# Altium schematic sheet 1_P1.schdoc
size 307 x 518 mm; Symbol: Drawing-Symbol_A4; Device: Drawing-Symbol_A4; @Project Name: LED tower pcb; @Page Count: 1; @Update Date: 2025-07-10; @Create Date: 2025-07-10; @Schematic Name: Schematic3; @Page No: 1; @Page Name: P1; Company: EasyEDA.com; Version: V1.0; Page Size: A4; @Create Time: 04:32:52; @Update Time: 00:32:52; Width: 1170; Height: 2000; Region Start: 1; X Region Count: 6; Y Region Count: 4; Blade Width: 10; Title Block Position: 3; @Board Name: Board3
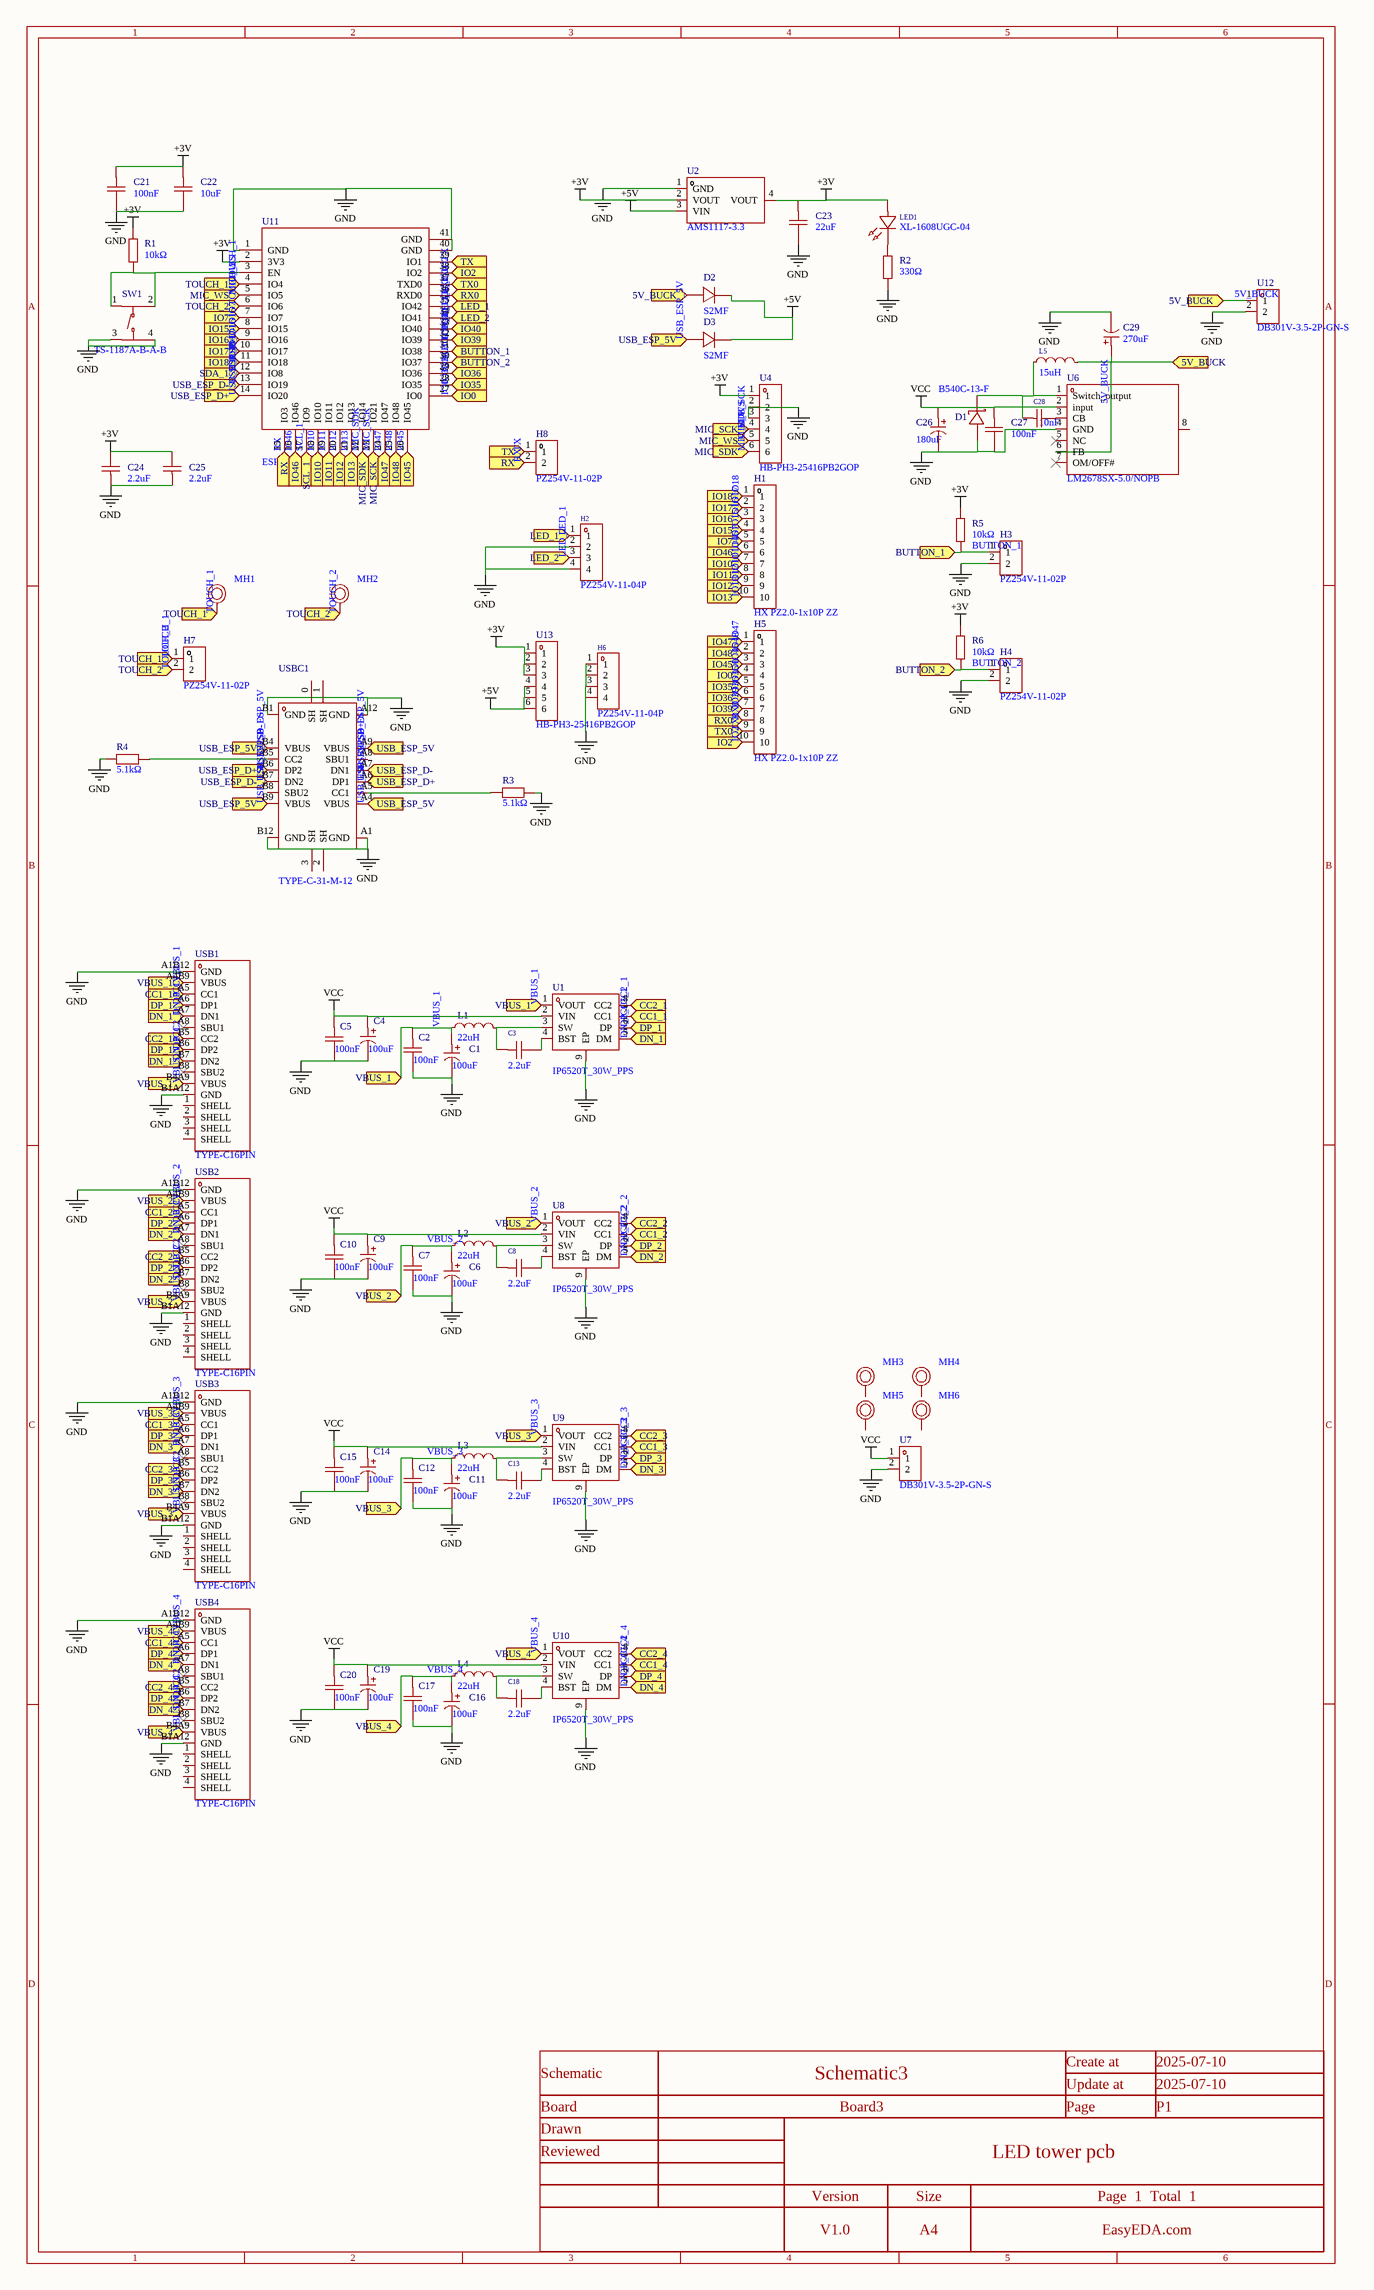
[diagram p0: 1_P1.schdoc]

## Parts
C1  100uF  [CAP-SMD_BD6.3-L6.6-W6.6-LS7.4-FD]
C2  100nF  [C0603]
C3  2.2uF  [C0603]
C4  100uF  [CAP-SMD_BD6.3-L6.6-W6.6-LS7.4-FD]
C5  100nF  [C0603]
C6  100uF  [CAP-SMD_BD6.3-L6.6-W6.6-LS7.4-FD]
C7  100nF  [C0603]
C8  2.2uF  [C0603]
C9  100uF  [CAP-SMD_BD6.3-L6.6-W6.6-LS7.4-FD]
C10  100nF  [C0603]
C11  100uF  [CAP-SMD_BD6.3-L6.6-W6.6-LS7.4-FD]
C12  100nF  [C0603]
C13  2.2uF  [C0603]
C14  100uF  [CAP-SMD_BD6.3-L6.6-W6.6-LS7.4-FD]
C15  100nF  [C0603]
C16  100uF  [CAP-SMD_BD6.3-L6.6-W6.6-LS7.4-FD]
C17  100nF  [C0603]
C18  2.2uF  [C0603]
C19  100uF  [CAP-SMD_BD6.3-L6.6-W6.6-LS7.4-FD]
C20  100nF  [C0603]
C21  100nF  [C0603]
C22  10uF  [C0603]
C23  22uF  [C0603]
C24  2.2uF  [C0805]
C25  2.2uF  [C0805]
C26  180uF  [CAP-SMD_BD10.0-L10.3-W10.3-FD]
C27  100nF  [C0603]
C28  10nF  [C0603]
C29  270uF  [CAP-SMD_BD10.0-L10.3-W10.3-FD-1]
D1  B540C-13-F  [SMC_L7.1-W6.2-LS8.1-RD]
D2  S2MF  [SMAF_L3.5-W2.6-LS4.7-RD]
D3  S2MF  [SMAF_L3.5-W2.6-LS4.7-RD]
H1  HX PZ2.0-1x10P ZZ  [HDR-TH_10P-P2.00-V-M-1]
H2  PZ254V-11-04P  [HDR-TH_4P-P2.54-V-M]
H3  PZ254V-11-02P  [HDR-TH_2P-P2.54-V-M]
H4  PZ254V-11-02P  [HDR-TH_2P-P2.54-V-M]
H5  HX PZ2.0-1x10P ZZ  [HDR-TH_10P-P2.00-V-M-1]
H6  PZ254V-11-04P  [HDR-TH_4P-P2.54-V-M]
H7  PZ254V-11-02P  [HDR-TH_2P-P2.54-V-M]
H8  PZ254V-11-02P  [HDR-TH_2P-P2.54-V-M]
L1  22uH  [IND-SMD_L11.5-W10.0_SMMS1040]
L2  22uH  [IND-SMD_L11.5-W10.0_SMMS1040]
L3  22uH  [IND-SMD_L11.5-W10.0_SMMS1040]
L4  22uH  [IND-SMD_L11.5-W10.0_SMMS1040]
L5  15uH  [IND-SMD_L12.0-W12.0_SLH1207S100MTT]
LED1  XL-1608UGC-04  [LED0603-RD_GREEN]
MH1  (no value)  [M3_Hole]
MH2  (no value)  [M3_Hole]
MH3  (no value)  [M3_Hole]
MH4  (no value)  [M3_Hole]
MH5  (no value)  [M3_Hole]
MH6  (no value)  [M3_Hole]
R1  10kΩ  [R0603]
R2  330Ω  [R0603]
R3  5.1kΩ  [R0603]
R4  5.1kΩ  [R0603]
R5  10kΩ  [R0603]
R6  10kΩ  [R0603]
SW1  TS-1187A-B-A-B  [SW-SMD_4P-L5.1-W5.1-P3.70-LS6.5-TL_H1.5]
U1  IP6520T_30W_PPS  [ESOP-8_L4.9-W3.9-P1.27-LS6.0-BL-EP3.1]
U2  AMS1117-3.3  [SOT-223-3_L6.5-W3.4-P2.30-LS7.0-BR]
U4  HB-PH3-25416PB2GOP  [HDR-TH_6P-P2.54-V-M]
U6  LM2678SX-5.0/NOPB  [TO-263-7_L10.2-W8.6-P1.27-LS14.4-TL]
U7  DB301V-3.5-2P-GN-S  [CONN-TH_DB301V-3.5-2P-GN]
U8  IP6520T_30W_PPS  [ESOP-8_L4.9-W3.9-P1.27-LS6.0-BL-EP3.1]
U9  IP6520T_30W_PPS  [ESOP-8_L4.9-W3.9-P1.27-LS6.0-BL-EP3.1]
U10  IP6520T_30W_PPS  [ESOP-8_L4.9-W3.9-P1.27-LS6.0-BL-EP3.1]
U11  ESP32-S3-WROOM-1U-N16R2  [WIRELM-SMD_ESP32-S3-WROOM-1U]
U12  DB301V-3.5-2P-GN-S  [CONN-TH_DB301V-3.5-2P-GN]
U13  HB-PH3-25416PB2GOP  [HDR-TH_6P-P2.54-V-M]
USB1  TYPE-C16PIN  [USB-C-SMD_TYPE-C16PIN]
USB2  TYPE-C16PIN  [USB-C-SMD_TYPE-C16PIN]
USB3  TYPE-C16PIN  [USB-C-SMD_TYPE-C16PIN]
USB4  TYPE-C16PIN  [USB-C-SMD_TYPE-C16PIN]
USBC1  TYPE-C-31-M-12  [USB-C_SMD-TYPE-C-31-M-12]

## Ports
5V_BUCK (in), BUTTON_1 (in), BUTTON_2 (in), CC1_1 (in), CC1_2 (in), CC1_3 (in), CC1_4 (in), CC2_1 (in), CC2_2 (in), CC2_3 (in), CC2_4 (in), DN_1 (in), DN_2 (in), DN_3 (in), DN_4 (in), DP_1 (in), DP_2 (in), DP_3 (in), DP_4 (in), IO0 (in), IO2 (in), IO7 (in), IO10 (in), IO11 (in), IO12 (in), IO13 (in), IO15 (in), IO16 (in), IO17 (in), IO18 (in), IO35 (in), IO36 (in), IO39 (in), IO40 (in), IO45 (in), IO46 (in), IO47 (in), IO48 (in), LED_1 (in), LED_2 (in), MIC_SCK (in), MIC_SDK (in), MIC_WS (in), RX0 (in), RX (in), SCL_1 (in), SDA_1 (in), TOUCH_1 (in), TOUCH_2 (in), TX0 (in), TX (in), USB_ESP_5V (in), USB_ESP_D+ (in), USB_ESP_D- (in), VBUS_1 (in), VBUS_2 (in), VBUS_3 (in), VBUS_4 (in)

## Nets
+3V: C21.2 C22.2 C23.2 C24.2 C25.2 LED1.2(A) R1.2 R5.2 R6.2 U2.2(VOUT) U2.4(VOUT) U4.1 U11.2(3V3) U13.1 U13.2 U13.3
+5V: D2.1(C) D3.1(C) U2.3(VIN) U13.4 U13.5 U13.6
GND: C1.2 C2.1 C4.2 C5.1 C6.2 C7.1 C9.2 C10.1 C11.2 C12.1 C14.2 C15.1 C16.2 C17.1 C19.2 C20.1 C21.1 C22.1 C23.1 C24.1 C25.1 C26.2 C27.1 C29.2 D1.2(A) H2.2 H2.4 H3.2 H4.2 H6.1 H6.2 H6.3 H6.4 R2.1 R3.2 R4.1 SW1.3(C) SW1.4(D) U1.9(EP) U2.1(GND) U4.2 U4.3 U6.4(GND) U7.2 U8.9(EP) U9.9(EP) U10.9(EP) U11.1(GND) U11.40(GND) U11.41(GND) U12.2 USB1.A1B12(GND) USB1.B1A12(GND) USB2.A1B12(GND) USB2.B1A12(GND) USB3.A1B12(GND) USB3.B1A12(GND) USB4.A1B12(GND) USB4.B1A12(GND) USBC1.A1(GND) USBC1.A12(GND) USBC1.B1(GND) USBC1.B12(GND)
VCC: C4.1 C5.2 C9.1 C10.2 C14.1 C15.2 C19.1 C20.2 C26.1 C27.2 U1.2(VIN) U6.2(input) U7.1 U8.2(VIN) U9.2(VIN) U10.2(VIN)
5V_BUCK: C29.1 D2.2(A) L5.2 U6.6(FB) U12.1 ; port 5V_BUCK
BUTTON_1: H3.1 R5.1 U11.31(IO38) ; port BUTTON_1
BUTTON_2: H4.1 R6.1 U11.30(IO37) ; port BUTTON_2
CC1_1: U1.7(CC1) USB1.A5(CC1) ; port CC1_1
CC1_2: U8.7(CC1) USB2.A5(CC1) ; port CC1_2
CC1_3: U9.7(CC1) USB3.A5(CC1) ; port CC1_3
CC1_4: U10.7(CC1) USB4.A5(CC1) ; port CC1_4
CC2_1: U1.8(CC2) USB1.B5(CC2) ; port CC2_1
CC2_2: U8.8(CC2) USB2.B5(CC2) ; port CC2_2
CC2_3: U9.8(CC2) USB3.B5(CC2) ; port CC2_3
CC2_4: U10.8(CC2) USB4.B5(CC2) ; port CC2_4
DN_1: U1.5(DM) USB1.A7(DN1) USB1.B7(DN2) ; port DN_1
DN_2: U8.5(DM) USB2.A7(DN1) USB2.B7(DN2) ; port DN_2
DN_3: U9.5(DM) USB3.A7(DN1) USB3.B7(DN2) ; port DN_3
DN_4: U10.5(DM) USB4.A7(DN1) USB4.B7(DN2) ; port DN_4
DP_1: U1.6(DP) USB1.A6(DP1) USB1.B6(DP2) ; port DP_1
DP_2: U8.6(DP) USB2.A6(DP1) USB2.B6(DP2) ; port DP_2
DP_3: U9.6(DP) USB3.A6(DP1) USB3.B6(DP2) ; port DP_3
DP_4: U10.6(DP) USB4.A6(DP1) USB4.B6(DP2) ; port DP_4
IO0: H5.4 U11.27(IO0) ; port IO0
IO2: H5.10 U11.38(IO2) ; port IO2
IO7: H1.5 U11.7(IO7) ; port IO7
IO10: H1.7 U11.18(IO10) ; port IO10
IO11: H1.8 U11.19(IO11) ; port IO11
IO12: H1.9 U11.20(IO12) ; port IO12
IO13: H1.10 U11.21(IO13) ; port IO13
IO15: H1.4 U11.8(IO15) ; port IO15
IO16: H1.3 U11.9(IO16) ; port IO16
IO17: H1.2 U11.10(IO17) ; port IO17
IO18: H1.1 U11.11(IO18) ; port IO18
IO35: H5.5 U11.28(IO35) ; port IO35
IO36: H5.6 U11.29(IO36) ; port IO36
IO39: H5.7 U11.32(IO39) ; port IO39
IO40: U11.33(IO40) ; port IO40
IO45: H5.3 U11.26(IO45) ; port IO45
IO46: H1.6 U11.16(IO46) ; port IO46
IO47: H5.1 U11.24(IO47) ; port IO47
IO48: H5.2 U11.25(IO48) ; port IO48
LED_1: H2.1 U11.35(IO42) ; port LED_1
LED_2: H2.3 U11.34(IO41) ; port LED_2
MIC_SCK: U4.4 U11.23(IO21) ; port MIC_SCK
MIC_SDK: U4.6 U11.22(IO14) ; port MIC_SDK
MIC_WS: U4.5 U11.5(IO5) ; port MIC_WS
RX: H8.2 U11.15(IO3) ; port RX
RX0: H5.8 U11.36(RXD0) ; port RX0
SCL_1: U11.17(IO9) ; port SCL_1
SDA_1: U11.12(IO8) ; port SDA_1
TOUCH_1: H7.1 MH1.1 U11.4(IO4) ; port TOUCH_1
TOUCH_2: H7.2 MH2.1 U11.6(IO6) ; port TOUCH_2
TX: H8.1 U11.39(IO1) ; port TX
TX0: H5.9 U11.37(TXD0) ; port TX0
USB_ESP_5V: D3.2(A) USBC1.A4(VBUS) USBC1.A9(VBUS) USBC1.B4(VBUS) USBC1.B9(VBUS) ; port USB_ESP_5V
USB_ESP_D+: U11.14(IO20) USBC1.A6(DP1) USBC1.B6(DP2) ; port USB_ESP_D+
USB_ESP_D-: U11.13(IO19) USBC1.A7(DN1) USBC1.B7(DN2) ; port USB_ESP_D-
VBUS_1: C1.1 C2.2 L1.1 U1.1(VOUT) USB1.A4B9(VBUS) USB1.B4A9(VBUS) ; port VBUS_1
VBUS_2: C6.1 C7.2 L2.1 U8.1(VOUT) USB2.A4B9(VBUS) USB2.B4A9(VBUS) ; port VBUS_2
VBUS_3: C11.1 C12.2 L3.1 U9.1(VOUT) USB3.A4B9(VBUS) USB3.B4A9(VBUS) ; port VBUS_3
VBUS_4: C16.1 C17.2 L4.1 U10.1(VOUT) USB4.A4B9(VBUS) USB4.B4A9(VBUS) ; port VBUS_4
NetC3_1: C3.1 U1.4(BST)
NetC3_2: C3.2 L1.2 U1.3(SW)
NetC8_1: C8.1 U8.4(BST)
NetC8_2: C8.2 L2.2 U8.3(SW)
NetC13_1: C13.1 U9.4(BST)
NetC13_2: C13.2 L3.2 U9.3(SW)
NetC18_1: C18.1 U10.4(BST)
NetC18_2: C18.2 L4.2 U10.3(SW)
NetC28_1: C28.1 D1.1(K) L5.1 U6.1(Switch_output)
NetC28_2: C28.2 U6.3(CB)
NetLED1_1: LED1.1(K) R2.2
NetR1_1: R1.1 SW1.1(A) SW1.2(B) U11.3(EN)
NetR3_1: R3.1 USBC1.A5(CC1)
NetR4_2: R4.2 USBC1.B5(CC2)

Not connected (* = marked no-connect by the designer): MH3 1; MH4 1; MH5 1; MH6 1; U6 5(NC)* 7(OM/OFF#)* 8; USB1 1(SHELL) 2(SHELL) 3(SHELL) 4(SHELL) A8(SBU1)* B8(SBU2)*; USB2 1(SHELL) 2(SHELL) 3(SHELL) 4(SHELL) A8(SBU1)* B8(SBU2)*; USB3 1(SHELL) 2(SHELL) 3(SHELL) 4(SHELL) A8(SBU1)* B8(SBU2)*; USB4 1(SHELL) 2(SHELL) 3(SHELL) 4(SHELL) A8(SBU1)* B8(SBU2)*; USBC1 0(SH) 1(SH) 2(SH) 3(SH) A8(SBU1) B8(SBU2)

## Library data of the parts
C1 C4 C6 C9 C11 C14 C16 C19 = RVT100UF35V67RV0034: Manufacturer: KNSCHA(科尼盛); Add into BOM: yes; Tolerance: ±20%; Ripple Current: 87mA@120kHz; Lifetime @ Temp: 2000hrs@105℃
C2 C5 C7 C10 C12 C15 C17 C20 C21 C27 = CC0603KRX7R9BB104: Manufacturer: YAGEO(国巨); Add into BOM: yes; Tolerance: ±10%; Voltage Rating: 50V; Temperature Coefficient: X7R
C3 C8 C13 C18 = UMK107BBJ225KA-T: Manufacturer: TAIYO YUDEN(太诱); Add into BOM: yes; Tolerance: ±10%
C22 = CL10A106KP8NNNC: Manufacturer: SAMSUNG(三星); Add into BOM: yes; Tolerance: ±10%
C23 = CL10A226MP8NUNE: Manufacturer: SAMSUNG(三星); Add into BOM: yes; Tolerance: ±20%
C24 C25 = CL21B225KAFNNNE: Manufacturer: SAMSUNG(三星); Add into BOM: yes; Tolerance: ±10%
C26 = VMME1001H181MV: Manufacturer: Ymin(永铭); Add into BOM: yes; Tolerance: ±20%; Voltage Rating: 50V
C28 = CC0603KRX7R9BB103: Manufacturer: YAGEO(国巨); Add into BOM: yes; Tolerance: ±10%
C29 = RVT1H271M1010: Manufacturer: ROQANG(容强); Add into BOM: yes; Tolerance: ±20%; Voltage Rating: 50V
D1 = B540C-13-F: Manufacturer: DIODES(美台); Add into BOM: yes; Forward Voltage (Vf@If): 550mV@5A; Reverse Voltage (Vr): 40V; Average Rectified Current (Io): 5A; Reverse Leakage Current (Ir): 500uA@40V
D2 D3 = S2MF_C908416: Manufacturer: GOODWORK(固得沃克); Add into BOM: yes; Diode Configuration: Independent Type; Voltage - Forward(Vf@If): 1.1V@2A; Voltage - DC Reverse(Vr): 1kV; Current - Rectified: 2A; Reverse Leakage Current (Ir): 5uA@1kV
H1 H5 = HX PZ2.0-1x10P ZZ: Manufacturer: hanxia(韩下); Add into BOM: yes; Pin Structure: 1x10P; Pitch: 2mm; Circluar Pins/Square Pins: Policy; Current Rating: 1.5A
H2 H6 = PZ254V-11-04P: Manufacturer: XFCN(兴飞); Symbol: PZ254V-11-04P_C2691448; Add into BOM: yes; Pin Structure: 1x4P; Pitch: 2.54mm; Circluar Pins/Square Pins: Square Pins; Current Rating (Max): 3A; Voltage Rating (Max): 250V
H3 H4 H7 H8 = PZ254V-11-02P: Manufacturer: XFCN(兴飞); Add into BOM: yes; Pin Structure: 1x2P; Pitch: 2.54mm; Circluar Pins/Square Pins: Policy
L1-L4 = SMMS1040-220M: Manufacturer: SXN(顺翔诺); Add into BOM: yes; Tolerance: ±20%; Saturation Current (Isat): 6A; Type: 一体成型电感
L5 = MSS1210-334KED: Manufacturer: Coilcraft(线艺); Manufacturer Part: MSS1210-153MED; Add into BOM: yes; Tolerance: ±10%
LED1 = XL-1608UGC-04: Manufacturer: XINGLIGHT(成兴光); Add into BOM: yes; Emitted Color: Emerald; Power Dissipation: 80mW; Forward Current: 25mA; Dominant Wavelength: 516nm~525nm; Peak Wavelength: 534nm; Diode Configuration: 独立二极管; Lens Color: 无色透明透镜; Viewing Angle: 120°; Mounting Sytle: Positive post
MH1-MH6 = M3_Hole: Add into BOM: no; Convert to PCB: yes
R1 R5 R6 = RC0603FR-0710KL: Manufacturer: YAGEO(国巨); Add into BOM: yes; Tolerance: ±1%; Temperature Coefficient: ±100ppm/℃
R2 = RC0603FR-07330RL: Manufacturer: YAGEO(国巨); Add into BOM: yes; Tolerance: ±1%; Temperature Coefficient: ±100ppm/℃
R3 R4 = RC0603FR-075K1L: Manufacturer: YAGEO(国巨); Add into BOM: yes; Tolerance: ±1%; Power(Watts): 100mW; Voltage-Supply(Max): 75V; Temperature Coefficient: ±100ppm/℃
SW1 = TS-1187A-B-A-B: Manufacturer: XKB Connectivity(中国星坤); Add into BOM: yes; Circuit: SPST; Actuator Style: Round Button; Operating Force: 160gf; Switch Length: 5.1mm; Switch Height: 1.5mm; Strike Gundam: 不带; Contact Current: 50mA; Voltage Rating (DC): 12V; Actuator/Cap Color: 金色; With Lamp: No; Mechanical Life: 10万次
U1 U8-U10 = IP6520T_30W_PPS: Manufacturer: INJOINIC(英集芯); Add into BOM: yes
U2 = AMS1117-3.3_C6186: Manufacturer: AMS; Add into BOM: yes; Output Type: Fixed; Voltage - Supply: 16V; Output Voltage: 3.3V; Output Current: 1A; Power Supply Rejection Ratio (PSRR): 72dB@(120Hz); Voltage Dropout: 1.1V@(800mA); standby current: 5mA; Output Configuration: Positive; Number of Outputs: 1
U4 U13 = HB-PH3-25416PB2GOP: Manufacturer: HANBO(汉博); Add into BOM: yes; Pin Structure: 1x6P; Pitch: 2.54mm; Circluar Pins/Square Pins: Policy; Current Rating: 3A; Voltage Rating (Max): 250V
U6 = LM2678SX-5.0/NOPB: Manufacturer: TI(德州仪器); Add into BOM: yes; Function: Step-down type; Output Type: Fixed; Voltage - Supply: 8V~40V; Output Voltage: 5V; Output Current: 5A; Frequency - Switching: 260kHz; Synchronous Rectifier: NONE; Number of Outputs: 1; Topology: Step-down; Switch tube (built-in/external): Built-in
U7 U12 = DB301V-3.5-2P-GN-S: Manufacturer: DORABO(地博电气); Add into BOM: yes; Number of Positions or Pins: 1x2P; Pitch: 3.5mm; Number of PINs Per Row: 2; Screw Specification: M2; Current Rating: 7A; Voltage Rating (Max): 300V
U11 = ESP32-S3-WROOM-1U-N16R2: Manufacturer: ESPRESSIF(乐鑫); Add into BOM: yes
USB1-USB4 = TYPE-C16PIN: Manufacturer: SHOU HAN(首韩); Add into BOM: yes; Connector Type: Type-C; Protocol Standard: USB 3.1; Gender: Female; Number of Contacts: 16P; Number of Ports: 1; Current Rating-Power: 3A; Voltage Rating: 30V; Connect-Disconnect Life: 10,000 Cycles; Detection color: Black
USBC1 = TYPE-C-31-M-12: Manufacturer: 韩国韩荣; Add into BOM: yes; Connector Type: Type-C; Gender: Female; Number of Contacts: 16P; Number of Ports: 1; Current Rating - Power (Max): 5A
